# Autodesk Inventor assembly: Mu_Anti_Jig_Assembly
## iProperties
Shininess: 64.0
Length Units: 11272
Angle Units: 11279
Time Units: 11290
Mass Units: 11286
Length Display Precision: 3
Angle Display Precision: 2
Compacted: True
Part Number: Mu_Anti_Jig_Assembly
Document SubType Name: Assembly
Created: 2004-08
Designer: John Blackburn
Manufacturer: Standard
Standards Organization: Custom
Density: 0.0
Volumn: 0.0
Area: 0.0
PropertySet Name: Model Information
Control State: 0
Master: False
Checked Out: False
Author: John Blackburn
